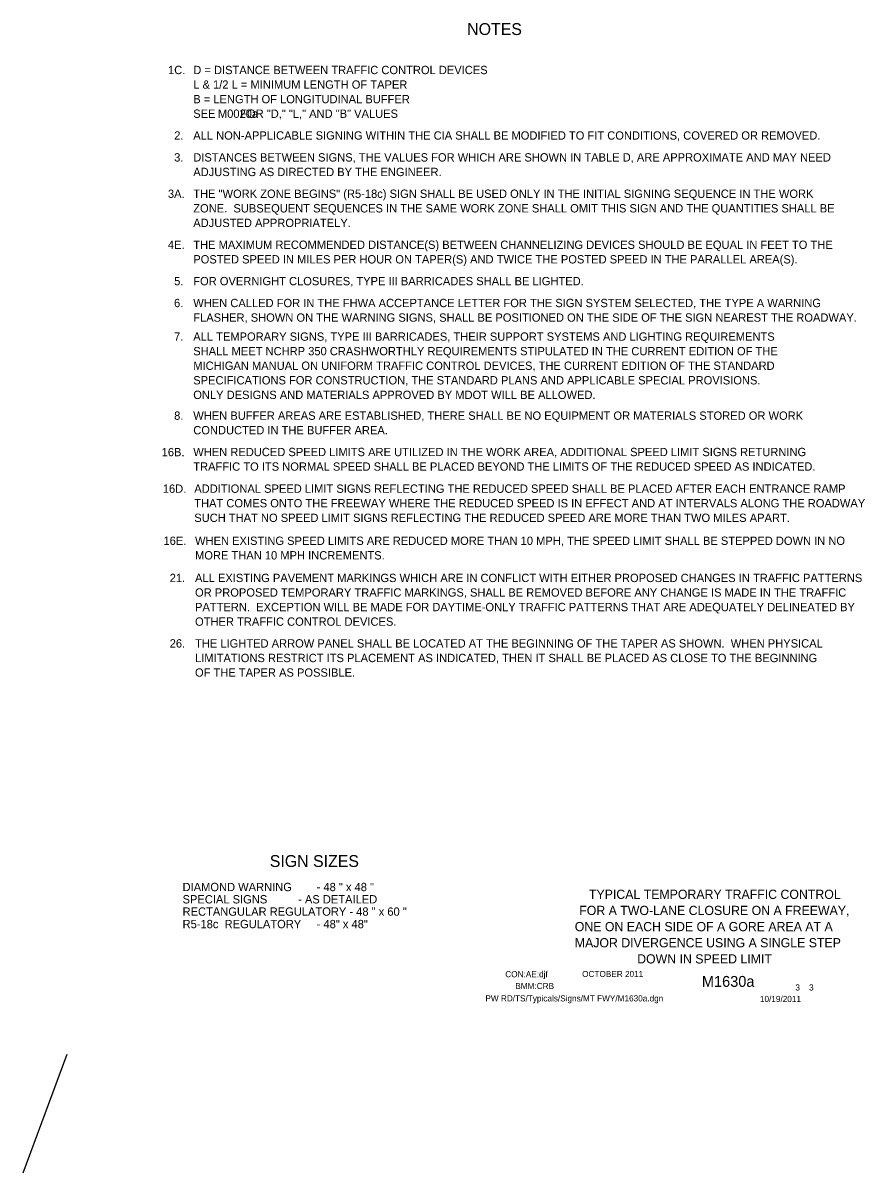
# Model space of a CAD drawing. Extents: x 16512 to 19512, y 5761 to 6974.
# Drawn here: x 18661 to 19512, y 5761 to 6921 of the extents above; entities that cross this region are included whole.
import ezdxf

# ---------------------------------------------------------------- set-up
doc = ezdxf.new("R2010")
doc.units = 0
for name, color, linetype in [('BORDER', 7, 'Continuous'), ('BORDER_SIGNAL_WO', 7, 'Continuous'), ('TYPICAL_TEXT_DIMEN_PR', 7, 'Continuous')]:
    doc.layers.add(name, color=color, linetype=linetype)

msp = doc.modelspace()

# ---------------------------------------------------------------- linework, layer by layer
at = {"layer": 'TYPICAL_TEXT_DIMEN_PR'}
msp.add_line((18705.8, 5880), (18661.5, 5760.5), dxfattribs=at)

# ---------------------------------------------------------------- texts
at = {"layer": 'BORDER'}
for s, p in [('TYPICAL TEMPORARY TRAFFIC CONTROL', (19233.2, 6037.2)), ('FOR A TWO-LANE CLOSURE ON A FREEWAY,', (19223.4, 6020.9)), ('ONE ON EACH SIDE OF A GORE AREA AT A ', (19218.9, 6004.6)), ('MAJOR DIVERGENCE USING A SINGLE STEP ', (19218.9, 5988.3)), ('DOWN IN SPEED LIMIT', (19281.9, 5972))]:
    msp.add_text(s, height=9.3, dxfattribs=at).set_placement(p)
at = {"layer": 'BORDER_SIGNAL_WO'}
for s, height, p in [('CON:AE:djf  ', 6.2, (19148.7, 5958.1)), ('    OCTOBER 2011    ', 6.2, (19217.1, 5958.3)), ('    M1630a   ', 11, (19330.9, 5948.4)), ('BMM:CRB   ', 6.2, (19158.8, 5946.2)), (' 3    3 ', 6.2, (19439.4, 5944.7)), ('PW RD/TS/Typicals/Signs/MT FWY/M1630a.dgn      ', 6.2, (19128.6, 5933.7)), ('10/19/2011    ', 6.2, (19405.9, 5933.1))]:
    msp.add_text(s, height=height, dxfattribs=at).set_placement(p)
at = {"layer": 'TYPICAL_TEXT_DIMEN_PR'}
for s, height, p in [('NOTES', 12, (19110.2, 6909.2)), ('1C.', 8.4, (18808, 6869.7)), ('D = DISTANCE BETWEEN TRAFFIC CONTROL DEVICES', 8.4, (18833.5, 6869.7)), ('L & 1/2 L = MINIMUM LENGTH OF TAPER', 8.4, (18833.5, 6855)), ('B = LENGTH OF LONGITUDINAL BUFFER', 8.4, (18833.5, 6840.3)), ('SEE        FOR "D," "L," AND "B" VALUES', 8.4, (18833.5, 6825.6)), ('M0020a', 8.4, (18858.4, 6825.6)), ('2.', 8.4, (18814.2, 6803.6)), ('ALL NON-APPLICABLE SIGNING WITHIN THE CIA SHALL BE MODIFIED TO FIT CONDITIONS, COVERED OR REMOVED.', 8.4, (18833.5, 6803.6)), ('3.', 8.4, (18814.2, 6781.5)), ('DISTANCES BETWEEN SIGNS, THE VALUES FOR WHICH ARE SHOWN IN TABLE D, ARE APPROXIMATE AND MAY NEED', 8.4, (18833.5, 6781.5)), ('ADJUSTING AS DIRECTED BY THE ENGINEER.', 8.4, (18833.5, 6766.8)), ('3A.', 8.4, (18807.9, 6744.8)), ('THE "WORK ZONE BEGINS" (R5-18c) SIGN SHALL BE USED ONLY IN THE INITIAL SIGNING SEQUENCE IN THE WORK', 8.4, (18833.5, 6744.8)), ('ZONE.  SUBSEQUENT SEQUENCES IN THE SAME WORK ZONE SHALL OMIT THIS SIGN AND THE QUANTITIES SHALL BE', 8.4, (18833.5, 6730.1)), ('ADJUSTED APPROPRIATELY.', 8.4, (18833.5, 6715.4)), ('4E.', 8.4, (18807.9, 6693.3)), ('THE MAXIMUM RECOMMENDED DISTANCE(S) BETWEEN CHANNELIZING DEVICES SHOULD BE EQUAL IN FEET TO THE', 8.4, (18833.5, 6693.3)), ('POSTED SPEED IN MILES PER HOUR ON TAPER(S) AND TWICE THE POSTED SPEED IN THE PARALLEL AREA(S).', 8.4, (18833.5, 6678.6)), ('5.', 8.4, (18814.2, 6656.6)), ('FOR OVERNIGHT CLOSURES, TYPE III BARRICADES SHALL BE LIGHTED. ', 8.4, (18833.5, 6656.6)), ('6.', 8.4, (18814.1, 6634.5)), ('WHEN CALLED FOR IN THE FHWA ACCEPTANCE LETTER FOR THE SIGN SYSTEM SELECTED, THE TYPE A WARNING ', 8.4, (18833.5, 6634.5)), ('FLASHER, SHOWN ON THE WARNING SIGNS, SHALL BE POSITIONED ON THE SIDE OF THE SIGN NEAREST THE ROADWAY.', 8.4, (18833.5, 6619.8)), ('7.', 8.4, (18814.1, 6600.6)), ('ALL TEMPORARY SIGNS, TYPE III BARRICADES, THEIR SUPPORT SYSTEMS AND LIGHTING REQUIREMENTS', 8.4, (18833.5, 6600.6)), ('SHALL MEET NCHRP 350 CRASHWORTHLY REQUIREMENTS STIPULATED IN THE CURRENT EDITION OF THE', 8.4, (18833.5, 6585.9)), ('MICHIGAN MANUAL ON UNIFORM TRAFFIC CONTROL DEVICES, THE CURRENT EDITION OF THE STANDARD', 8.4, (18833.5, 6571.2)), ('SPECIFICATIONS FOR CONSTRUCTION, THE STANDARD PLANS AND APPLICABLE SPECIAL PROVISIONS.', 8.4, (18833.5, 6556.5)), ('ONLY DESIGNS AND MATERIALS APPROVED BY MDOT WILL BE ALLOWED.', 8.4, (18833.5, 6541.8)), ('8.', 8.4, (18814.2, 6520.8)), ('WHEN BUFFER AREAS ARE ESTABLISHED, THERE SHALL BE NO EQUIPMENT OR MATERIALS STORED OR WORK     ', 8.4, (18833.5, 6520.8)), ('CONDUCTED IN THE BUFFER AREA.', 8.4, (18833.5, 6506.1)), ('16B.', 8.4, (18801.6, 6484)), ('WHEN REDUCED SPEED LIMITS ARE UTILIZED IN THE WORK AREA, ADDITIONAL SPEED LIMIT SIGNS RETURNING', 8.4, (18833.5, 6484.1)), ('TRAFFIC TO ITS NORMAL SPEED SHALL BE PLACED BEYOND THE LIMITS OF THE REDUCED SPEED AS INDICATED.', 8.4, (18833.5, 6469.4)), ('16D.', 8.4, (18802.7, 6447.1)), ('ADDITIONAL SPEED LIMIT SIGNS REFLECTING THE REDUCED SPEED SHALL BE PLACED AFTER EACH ENTRANCE RAMP', 8.4, (18834.5, 6447.1)), ('THAT COMES ONTO THE FREEWAY WHERE THE REDUCED SPEED IS IN EFFECT AND AT INTERVALS ALONG THE ROADWAY', 8.4, (18834.5, 6432.4)), ('SUCH THAT NO SPEED LIMIT SIGNS REFLECTING THE REDUCED SPEED ARE MORE THAN TWO MILES APART.', 8.4, (18834.5, 6417.7)), ('16E.', 8.4, (18803.4, 6394.5)), ('WHEN EXISTING SPEED LIMITS ARE REDUCED MORE THAN 10 MPH, THE SPEED LIMIT SHALL BE STEPPED DOWN IN NO', 8.4, (18835.3, 6394.5)), ('MORE THAN 10 MPH INCREMENTS.', 8.4, (18835.3, 6379.8)), ('21.', 8.4, (18809.7, 6357)), ('ALL EXISTING PAVEMENT MARKINGS WHICH ARE IN CONFLICT WITH EITHER PROPOSED CHANGES IN TRAFFIC PATTERNS', 8.4, (18835.3, 6357)), ('OR PROPOSED TEMPORARY TRAFFIC MARKINGS, SHALL BE REMOVED BEFORE ANY CHANGE IS MADE IN THE TRAFFIC', 8.4, (18835.3, 6342.3)), ('PATTERN.  EXCEPTION WILL BE MADE FOR DAYTIME-ONLY TRAFFIC PATTERNS THAT ARE ADEQUATELY DELINEATED BY', 8.4, (18835.3, 6327.6)), ('OTHER TRAFFIC CONTROL DEVICES.', 8.4, (18835.3, 6312.9)), ('26.', 8.4, (18809.7, 6290.9)), ('THE LIGHTED ARROW PANEL SHALL BE LOCATED AT THE BEGINNING OF THE TAPER AS SHOWN.  WHEN PHYSICAL', 8.4, (18835.3, 6290.9)), ('LIMITATIONS RESTRICT ITS PLACEMENT AS INDICATED, THEN IT SHALL BE PLACED AS CLOSE TO THE BEGINNING', 8.4, (18835.3, 6276.2)), ('OF THE TAPER AS POSSIBLE.', 8.4, (18835.3, 6261.5)), ('SIGN SIZES', 12, (18910.8, 6069.4)), ('DIAMOND WARNING        - 48 " x 48 "', 8.4, (18822.7, 6045)), ('SPECIAL SIGNS          - AS DETAILED', 8.4, (18822.7, 6032.6)), ('RECTANGULAR REGULATORY - 48 " x 60 "', 8.4, (18822.7, 6020.2)), ('R5-18c  REGULATORY     - 48" x 48"', 8.4, (18822.7, 6007.6))]:
    msp.add_text(s, height=height, dxfattribs=at).set_placement(p)

doc.saveas('drawing.dxf')
